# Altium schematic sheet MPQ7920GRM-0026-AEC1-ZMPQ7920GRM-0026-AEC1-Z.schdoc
size 127 x 101 mm
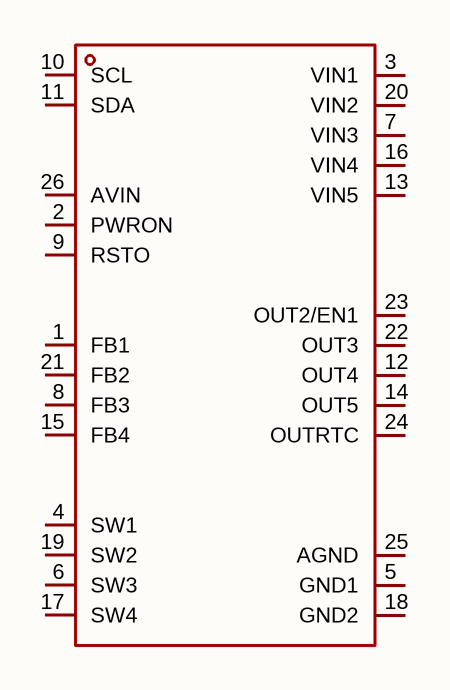
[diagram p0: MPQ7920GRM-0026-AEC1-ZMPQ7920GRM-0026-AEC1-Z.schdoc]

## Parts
U?  mpq7920grm-0026-aec1-z  [QFN-26_L4.5-W3.5-P0.45-BL]  (value not drawn)

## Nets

Not connected (* = marked no-connect by the designer): U? 1(FB1) 2(PWRON) 3(VIN1) 4(SW1) 5(GND1) 6(SW3) 7(VIN3) 8(FB3) 9(RSTO) 10(SCL) 11(SDA) 12(OUT4) 13(VIN5) 14(OUT5) 15(FB4) 16(VIN4) 17(SW4) 18(GND2) 19(SW2) 20(VIN2) 21(FB2) 22(OUT3) 23(OUT2/EN1) 24(OUTRTC) 25(AGND) 26(AVIN)

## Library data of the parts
U? = mpq7920grm-0026-aec1-z: 输出极性:正极;工作电压:5.5V;; Manufacturer: MPS(芯源); AddInBom: yes; Output Configuration: 正极; Voltage - Supply: 5.5V; Voltage Dropout: 50mV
